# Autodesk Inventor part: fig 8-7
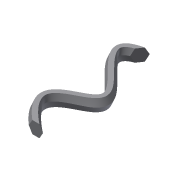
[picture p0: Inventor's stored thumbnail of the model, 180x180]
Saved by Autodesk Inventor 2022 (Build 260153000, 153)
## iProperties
Created: 2006-01
Part Number: fig 8-7
Document SubType Name: Modeling
Designer: CADCIM
Density: 1 g/cm^3
Material: Generic
Appearance: Default
Author: CADCIM
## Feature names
1. Sweep4
## Parameters: d3 = 0, d4 = 0
